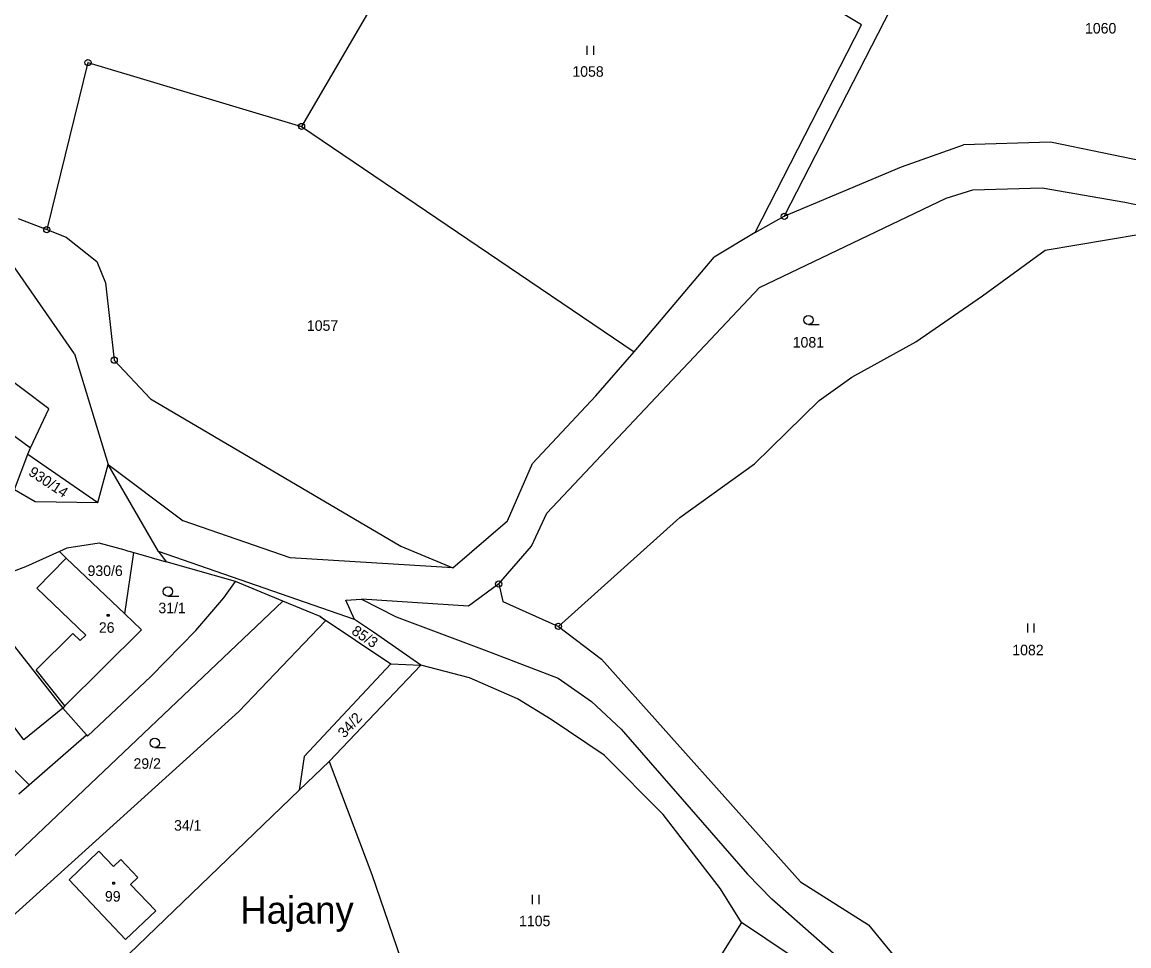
# Model space of a CAD drawing. Extents: x -796130 to -793145, y -1109506 to -1106267.
# Drawn here: x -794498.3 to -794319.4, y -1107652.3 to -1107503 of the extents above; entities that cross this region are included whole.
import ezdxf

# ---------------------------------------------------------------- set-up
doc = ezdxf.new("R2010")
doc.units = 0
for name, color, linetype in [('Vrstva 1', 7, 'Continuous'), ('Vrstva 14', 7, 'Continuous'), ('Vrstva 15', 7, 'Continuous'), ('Vrstva 2', 7, 'Continuous'), ('Vrstva 23', 7, 'Continuous'), ('Vrstva 25', 7, 'Continuous'), ('Vrstva 28', 7, 'Continuous'), ('Vrstva 36', 7, 'Continuous')]:
    doc.layers.add(name, color=color, linetype=linetype)

msp = doc.modelspace()

# ---------------------------------------------------------------- linework, layer by layer
at = {"layer": 'Vrstva 1'}
for p, q in [((-794362.64, -1107503.42), (-794423.33, -1107467.05)), ((-794342.34, -1107470.39), (-794375.12, -1107534.38)), ((-794428.03, -1107476.84), (-794453.14, -1107519.86)), ((-794379.84, -1107537.01), (-794362.64, -1107503.42)), ((-794487.66, -1107509.53), (-794494.32, -1107536.54)), ((-794487.66, -1107509.53), (-794453.14, -1107519.86)), ((-794453.14, -1107519.86), (-794399.39, -1107556.28)), ((-794332.08, -1107522.42), (-794346.13, -1107522.85)), ((-794285.56, -1107531.95), (-794332.08, -1107522.42)), ((-794356.19, -1107526.4), (-794346.13, -1107522.85)), ((-794375.12, -1107534.38), (-794356.19, -1107526.4)), ((-794344.66, -1107530.09), (-794333.42, -1107529.81)), ((-794333.42, -1107529.81), (-794320.09, -1107532.09)), ((-794379.12, -1107545.92), (-794348.93, -1107531.44)), ((-794348.93, -1107531.44), (-794344.66, -1107530.09)), ((-794320.09, -1107532.09), (-794310.47, -1107534.08)), ((-794498.93, -1107534.73), (-794494.32, -1107536.54)), ((-794379.84, -1107537.01), (-794375.12, -1107534.38)), ((-794494.32, -1107536.54), (-794491.17, -1107537.78)), ((-794379.84, -1107537.01), (-794386.47, -1107540.97)), ((-794489.84, -1107556.63), (-794502.58, -1107538.28)), ((-794491.17, -1107537.78), (-794486.25, -1107541.7)), ((-794332.95, -1107539.88), (-794317.6, -1107537.28)), ((-794343.09, -1107547.22), (-794332.95, -1107539.88)), ((-794486.25, -1107541.7), (-794484.85, -1107545.12)), ((-794399.39, -1107556.28), (-794386.47, -1107540.97)), ((-794484.85, -1107545.12), (-794483.42, -1107557.64)), ((-794413.5, -1107582.35), (-794379.12, -1107545.92)), ((-794353.83, -1107554.68), (-794343.09, -1107547.22)), ((-794364.21, -1107560.41), (-794353.83, -1107554.68)), ((-794494.01, -1107565.49), (-794507.12, -1107555.67)), ((-794489.84, -1107556.63), (-794484.4, -1107574.51)), ((-794405.58, -1107563.42), (-794399.39, -1107556.28)), ((-794483.42, -1107557.64), (-794477.56, -1107563.9)), ((-794369.48, -1107564.18), (-794364.21, -1107560.41)), ((-794415.82, -1107574.35), (-794405.58, -1107563.42)), ((-794496.93, -1107571.79), (-794494.01, -1107565.49)), ((-794477.56, -1107563.9), (-794437.09, -1107587.7)), ((-794379.92, -1107574.4), (-794369.48, -1107564.18)), ((-794499.55, -1107578.55), (-794497.4, -1107572.82)), ((-794497.4, -1107572.82), (-794496.93, -1107571.79)), ((-794497.4, -1107572.82), (-794486.06, -1107580.67)), ((-794486.06, -1107580.67), (-794484.4, -1107574.51)), ((-794476.24, -1107588.56), (-794484.4, -1107574.51)), ((-794484.4, -1107574.51), (-794472.27, -1107583.59)), ((-794419.88, -1107583.63), (-794415.82, -1107574.35)), ((-794391.99, -1107583.05), (-794379.92, -1107574.4)), ((-794499.55, -1107578.55), (-794496.18, -1107580.49)), ((-794496.18, -1107580.49), (-794486.06, -1107580.67)), ((-794415.95, -1107587.72), (-794413.5, -1107582.35)), ((-794411.62, -1107600.67), (-794391.99, -1107583.05)), ((-794455, -1107589.6), (-794472.27, -1107583.59)), ((-794428.67, -1107591.19), (-794419.88, -1107583.63)), ((-794492.27, -1107588.58), (-794497.77, -1107591.05)), ((-794491.1, -1107588.05), (-794492.27, -1107588.58)), ((-794492.27, -1107588.58), (-794491.19, -1107589.63)), ((-794485.87, -1107587.2), (-794491.1, -1107588.05)), ((-794481.63, -1107588.36), (-794485.87, -1107587.2)), ((-794481.72, -1107598.65), (-794480.27, -1107588.75)), ((-794481.63, -1107588.36), (-794480.27, -1107588.75)), ((-794480.27, -1107588.75), (-794475, -1107590.25)), ((-794444.59, -1107599.58), (-794476.24, -1107588.56)), ((-794476.24, -1107588.56), (-794475, -1107590.25)), ((-794437.09, -1107587.7), (-794428.67, -1107591.19)), ((-794421.27, -1107593.81), (-794415.95, -1107587.72)), ((-794491.19, -1107589.63), (-794481.72, -1107598.65)), ((-794463.81, -1107593.43), (-794475, -1107590.25)), ((-794428.67, -1107591.19), (-794455, -1107589.6)), ((-794497.77, -1107591.05), (-794501.58, -1107592.5)), ((-794465.68, -1107596.08), (-794463.81, -1107593.43)), ((-794456.16, -1107596.58), (-794463.81, -1107593.43)), ((-794421.27, -1107593.81), (-794426.14, -1107597.41)), ((-794421.27, -1107593.81), (-794420.6, -1107596.65)), ((-794506.46, -1107595.16), (-794491.75, -1107613.89)), ((-794470.21, -1107601.33), (-794465.68, -1107596.08)), ((-794456.16, -1107596.58), (-794505.16, -1107643.13)), ((-794450.11, -1107599.09), (-794456.16, -1107596.58)), ((-794445.98, -1107596.42), (-794443.44, -1107596.28)), ((-794444.59, -1107599.58), (-794445.98, -1107596.42)), ((-794426.14, -1107597.41), (-794443.44, -1107596.28)), ((-794443.44, -1107596.28), (-794437.87, -1107599.12)), ((-794420.6, -1107596.65), (-794411.62, -1107600.67)), ((-794481.72, -1107598.65), (-794479.03, -1107601.21)), ((-794449.26, -1107599.78), (-794450.11, -1107599.09)), ((-794450.11, -1107599.09), (-794438.73, -1107606.75)), ((-794441.51, -1107601.61), (-794444.59, -1107599.58)), ((-794437.87, -1107599.12), (-794423.62, -1107604.49)), ((-794479.03, -1107601.21), (-794491.39, -1107613.53)), ((-794477.48, -1107608.76), (-794470.21, -1107601.33)), ((-794463.29, -1107614.43), (-794449.26, -1107599.78)), ((-794411.62, -1107600.67), (-794404.64, -1107605.96)), ((-794433.87, -1107606.96), (-794441.51, -1107601.61)), ((-794423.62, -1107604.49), (-794411.67, -1107609.07)), ((-794438.73, -1107606.75), (-794433.87, -1107606.96)), ((-794404.64, -1107605.96), (-794372.52, -1107641.97)), ((-794433.87, -1107606.96), (-794448.66, -1107622.5)), ((-794426.01, -1107609), (-794433.87, -1107606.96)), ((-794487.72, -1107618.4), (-794477.48, -1107608.76)), ((-794418.24, -1107612.36), (-794426.01, -1107609)), ((-794411.67, -1107609.07), (-794406.27, -1107612.84)), ((-794491.39, -1107613.53), (-794491.75, -1107613.89)), ((-794491.75, -1107613.89), (-794487.89, -1107618.22)), ((-794412.78, -1107615.71), (-794418.24, -1107612.36)), ((-794406.27, -1107612.84), (-794401.48, -1107617.31)), ((-794501.05, -1107648.58), (-794463.29, -1107614.43)), ((-794404.25, -1107621.5), (-794412.78, -1107615.71)), ((-794401.48, -1107617.31), (-794383.62, -1107637.79)), ((-794497.15, -1107626.26), (-794487.89, -1107618.22)), ((-794487.89, -1107618.22), (-794487.72, -1107618.4)), ((-794448.66, -1107622.5), (-794453.53, -1107627.17)), ((-794448.66, -1107622.5), (-794441.8, -1107640.76)), ((-794394.7, -1107631.06), (-794404.25, -1107621.5)), ((-794498.85, -1107627.74), (-794497.15, -1107626.26)), ((-794482.48, -1107655.02), (-794453.53, -1107627.17)), ((-794385.43, -1107643.11), (-794394.7, -1107631.06)), ((-794490.72, -1107641.63), (-794485.9, -1107637.01)), ((-794485.9, -1107637.01), (-794483.55, -1107639.48)), ((-794483.55, -1107639.48), (-794482.37, -1107638.36)), ((-794482.37, -1107638.36), (-794479.6, -1107641.27)), ((-794383.62, -1107637.79), (-794381.09, -1107640.72)), ((-794441.8, -1107640.76), (-794436.37, -1107656.6)), ((-794381.09, -1107640.72), (-794377.15, -1107644.78)), ((-794481.6, -1107651.29), (-794490.72, -1107641.63)), ((-794479.6, -1107641.27), (-794480.78, -1107642.39)), ((-794480.78, -1107642.39), (-794476.71, -1107646.67)), ((-794372.52, -1107641.97), (-794361.53, -1107648.94)), ((-794382.04, -1107648.53), (-794385.43, -1107643.11)), ((-794363.6, -1107656.68), (-794377.15, -1107644.78)), ((-794476.71, -1107646.67), (-794481.6, -1107651.29)), ((-794382.04, -1107648.53), (-794402.09, -1107680.28)), ((-794365.2, -1107659.81), (-794382.04, -1107648.53)), ((-794361.53, -1107648.94), (-794339.86, -1107675.09))]:
    msp.add_line(p, q, dxfattribs=at)
msp.add_lwpolyline([(-794438.73, -1107606.75), (-794452.72, -1107621.71), (-794453.53, -1107627.17)], dxfattribs=at)
at = {"layer": 'Vrstva 2'}
for p, q in [((-794520.44, -1107554.68), (-794496.93, -1107571.79)), ((-794495.95, -1107594.48), (-794491.19, -1107589.63)), ((-794488.01, -1107602.09), (-794495.95, -1107594.48)), ((-794496.03, -1107607.7), (-794490.09, -1107601.84)), ((-794490.09, -1107601.84), (-794488.91, -1107602.97)), ((-794488.91, -1107602.97), (-794488.01, -1107602.09)), ((-794498.01, -1107619.02), (-794508.05, -1107605.7)), ((-794491.39, -1107613.53), (-794496.03, -1107607.7)), ((-794491.75, -1107613.89), (-794498.01, -1107619.02)), ((-794497.15, -1107626.26), (-794503.08, -1107620.45))]:
    msp.add_line(p, q, dxfattribs=at)
at = {"layer": 'Vrstva 23'}
for p, q in [((-794406.96, -1107508.31), (-794406.96, -1107506.81)), ((-794405.96, -1107506.81), (-794405.96, -1107508.31)), ((-794371.21, -1107551.9), (-794369.46, -1107551.9)), ((-794474.74, -1107595.79), (-794472.99, -1107595.79)), ((-794335.78, -1107601.68), (-794335.78, -1107600.18)), ((-794334.78, -1107600.18), (-794334.78, -1107601.68)), ((-794476.87, -1107620.26), (-794475.12, -1107620.26)), ((-794415.8, -1107645.56), (-794415.8, -1107644.06)), ((-794414.8, -1107644.06), (-794414.8, -1107645.56))]:
    msp.add_line(p, q, dxfattribs=at)
for centre in [(-794371.21, -1107551.15), (-794474.74, -1107595.04), (-794476.87, -1107619.51)]:
    msp.add_circle(centre, 0.75, dxfattribs=at)
at = {"layer": 'Vrstva 25'}
for p, q in [((-794484.56, -1107598.73), (-794484.26, -1107598.73)), ((-794484.56, -1107599.03), (-794484.56, -1107598.73)), ((-794484.26, -1107599.03), (-794484.56, -1107599.03)), ((-794484.26, -1107598.73), (-794484.26, -1107599.03)), ((-794483.67, -1107642.03), (-794483.37, -1107642.03)), ((-794483.67, -1107642.33), (-794483.67, -1107642.03)), ((-794483.37, -1107642.33), (-794483.67, -1107642.33)), ((-794483.37, -1107642.03), (-794483.37, -1107642.33))]:
    msp.add_line(p, q, dxfattribs=at)
at = {"layer": 'Vrstva 28'}
for centre, radius in [((-794487.66, -1107509.53), 0.5), ((-794487.66, -1107509.53), 0.01), ((-794453.14, -1107519.86), 0.5), ((-794453.14, -1107519.86), 0.01), ((-794375.12, -1107534.38), 0.5), ((-794375.12, -1107534.38), 0.01), ((-794494.32, -1107536.54), 0.5), ((-794494.32, -1107536.54), 0.01), ((-794483.42, -1107557.64), 0.5), ((-794483.42, -1107557.64), 0.01), ((-794421.27, -1107593.81), 0.5), ((-794421.27, -1107593.81), 0.01), ((-794411.62, -1107600.67), 0.5), ((-794411.62, -1107600.67), 0.01)]:
    msp.add_circle(centre, radius, dxfattribs=at)

# ---------------------------------------------------------------- texts
at = {"layer": 'Vrstva 14'}
for s, p in [('1060', (-794326.508, -1107504.84)), ('1058', (-794409.365, -1107511.83)), ('1057', (-794452.272, -1107552.9)), ('1081', (-794373.752, -1107555.6)), ('930/6', (-794487.73, -1107592.53)), ('31/1', (-794476.28, -1107598.54)), ('1082', (-794338.259, -1107605.34)), ('29/2', (-794480.3, -1107623.69)), ('34/1', (-794473.749, -1107633.69)), ('1105', (-794417.989, -1107649.14))]:
    msp.add_text(s, height=1.7, dxfattribs=at).set_placement(p)
for s, rotation, p in [('930/14', 326.56014, (-794497.41, -1107576.13)), ('85/3', 326.22552, (-794445.21, -1107601.79)), ('34/2', 47.42748, (-794446.214, -1107618.827))]:
    msp.add_text(s, height=1.7, rotation=rotation, dxfattribs=at).set_placement(p)
at = {"layer": 'Vrstva 15'}
for s, p in [('26', (-794485.9, -1107601.71)), ('99', (-794484.92, -1107645.16))]:
    msp.add_text(s, height=1.7, dxfattribs=at).set_placement(p)
at = {"layer": 'Vrstva 36'}
msp.add_text('Hajany', height=4.4, dxfattribs=at).set_placement((-794463.03, -1107648.73))

doc.saveas('drawing.dxf')
